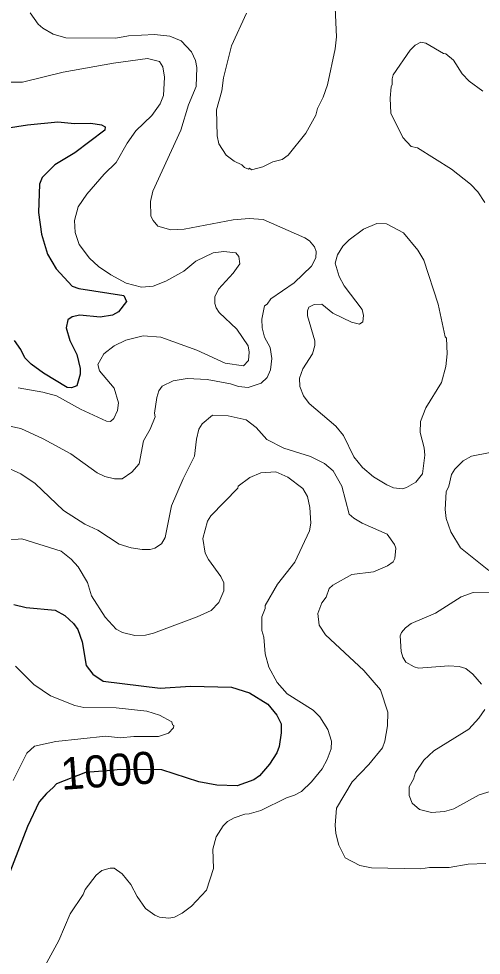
# Model space of a CAD drawing. Extents: x 447.8 to 473.9, y 7733.1 to 7760.8.
# Drawn here: x 455.425 to 456.578, y 7746.538 to 7748.871 of the extents above; entities that cross this region are included whole.
import ezdxf
from ezdxf.enums import TextEntityAlignment as Align

# ---------------------------------------------------------------- set-up
doc = ezdxf.new("R2010")
doc.units = 0
doc.header["$LTSCALE"] = 0.032
doc.layers.add('1', color=7, linetype='Continuous', lineweight=25)
doc.layers.add('2', color=7, linetype='Continuous', lineweight=13)
doc.layers.add('61', color=7, linetype='Continuous')

msp = doc.modelspace()

# ---------------------------------------------------------------- linework, layer by layer
at = {"layer": '1'}
for points in [[(455.3932, 7748.5984), (455.4461, 7748.6072), (455.5218, 7748.6144), (455.5635, 7748.6105), (455.6048, 7748.6111), (455.6308, 7748.6071), (455.6399, 7748.6018), (455.6394, 7748.5941), (455.5646, 7748.5376), (455.515, 7748.5077), (455.4827, 7748.4756), (455.4768, 7748.4588), (455.4738, 7748.3888), (455.4813, 7748.3348), (455.4964, 7748.2847), (455.5176, 7748.2483), (455.558, 7748.2048), (455.5747, 7748.199), (455.6864, 7748.1816), (455.6938, 7748.167), (455.6735, 7748.1409), (455.6584, 7748.133), (455.6275, 7748.1279), (455.5769, 7748.1326), (455.5575, 7748.1288), (455.5472, 7748.121), (455.5432, 7748.1015), (455.5525, 7748.0698), (455.5698, 7748.0352), (455.5779, 7747.9999), (455.578, 7747.9857), (455.5694, 7747.9568), (455.5561, 7747.9519), (455.5454, 7747.953), (455.4862, 7747.9883), (455.4556, 7748.0105), (455.4396, 7748.0266), (455.4298, 7748.0474), (455.4139, 7748.0695)], [(455.4124, 7747.4119), (455.4434, 7747.4048), (455.5155, 7747.3976), (455.5399, 7747.3843), (455.5611, 7747.3647), (455.5723, 7747.3499), (455.5827, 7747.319), (455.5929, 7747.2599), (455.6094, 7747.2386), (455.6348, 7747.2206), (455.7777, 7747.2037), (455.8532, 7747.2083), (455.9555, 7747.2059), (456.0001, 7747.1917), (456.0461, 7747.1635), (456.0685, 7747.1362), (456.0789, 7747.1151), (456.079, 7747.0924), (456.0741, 7747.0585), (456.0682, 7747.0421), (456.0501, 7747.0144), (456.025, 7746.9853), (456.011, 7746.9748), (455.9691, 7746.9602), (455.9188, 7746.9617), (455.8735, 7746.97), (455.7817, 7747), (455.6778, 7747.0006), (455.656, 7746.9988), (455.5913, 7746.9935), (455.5188, 7746.9649), (455.5109, 7746.9562), (455.4937, 7746.9414), (455.4754, 7746.9202), (455.4468, 7746.8588), (455.4021, 7746.7451)]]:
    msp.add_lwpolyline(points, dxfattribs=at)
at = {"layer": '2'}
for points in [[(455.4528, 7748.8864), (455.4733, 7748.8579), (455.4845, 7748.8475), (455.5107, 7748.8327), (455.5423, 7748.8239), (455.6669, 7748.8228), (455.6987, 7748.8283), (455.7632, 7748.8316), (455.8013, 7748.8276), (455.8296, 7748.8162), (455.8559, 7748.7886), (455.8657, 7748.7671), (455.8689, 7748.7501), (455.8672, 7748.7027), (455.8479, 7748.6571), (455.8287, 7748.5941), (455.7587, 7748.4414), (455.7536, 7748.4163), (455.7544, 7748.3796), (455.7599, 7748.3685), (455.7718, 7748.3548), (455.8042, 7748.3451), (455.8369, 7748.3471), (455.9594, 7748.3707), (455.9996, 7748.374), (456.0342, 7748.3715), (456.1381, 7748.3256), (456.1495, 7748.3177), (456.1621, 7748.3028), (456.1663, 7748.291), (456.1655, 7748.2753), (456.1548, 7748.255), (456.1116, 7748.2133), (456.0535, 7748.1735), (456.0438, 7748.1602), (456.0374, 7748.1563), (456.0312, 7748.1226), (456.0317, 7748.1015), (456.0377, 7748.0776), (456.0514, 7748.0519), (456.0558, 7748.0247), (456.0525, 7747.9963), (456.0439, 7747.9774), (456.0292, 7747.9635), (455.9972, 7747.9523), (455.9726, 7747.9552), (455.9526, 7747.9618), (455.8943, 7747.9724), (455.8448, 7747.9748), (455.8099, 7747.9692), (455.7826, 7747.9556), (455.7744, 7747.9447), (455.7688, 7747.9277), (455.7632, 7747.8889), (455.7646, 7747.8796), (455.7522, 7747.8487), (455.7359, 7747.8197), (455.7246, 7747.7623), (455.7068, 7747.742), (455.6828, 7747.7247), (455.6631, 7747.7247), (455.6391, 7747.7305), (455.6205, 7747.7401), (455.5547, 7747.7871), (455.4859, 7747.8248), (455.43, 7747.8503), (455.3722, 7747.8624)], [(455.9925, 7748.8848), (455.9554, 7748.8037), (455.9356, 7748.7244), (455.9313, 7748.6919), (455.9179, 7748.644), (455.9195, 7748.5796), (455.9238, 7748.5596), (455.9419, 7748.5312), (455.9622, 7748.5161), (455.9812, 7748.5074), (455.9873, 7748.5004), (455.9978, 7748.4968), (456.0005, 7748.4987), (456.0053, 7748.4951), (456.0335, 7748.5027), (456.0582, 7748.5149), (456.0815, 7748.5203), (456.0969, 7748.5314), (456.1409, 7748.5866), (456.1654, 7748.631), (456.1697, 7748.6475), (456.1839, 7748.6761), (456.1948, 7748.7066), (456.2136, 7748.7963), (456.2168, 7748.8262), (456.2137, 7748.8983)], [(456.5818, 7748.6906), (456.5479, 7748.7154), (456.5303, 7748.734), (456.5088, 7748.768), (456.49, 7748.7842), (456.4841, 7748.7847), (456.4402, 7748.8108), (456.4277, 7748.813), (456.4135, 7748.8053), (456.4011, 7748.7929), (456.3585, 7748.7317), (456.3556, 7748.7212), (456.3563, 7748.7076), (456.3532, 7748.7019), (456.3508, 7748.6735), (456.3528, 7748.636), (456.3825, 7748.5758), (456.4032, 7748.553), (456.4188, 7748.5494), (456.5036, 7748.4967), (456.5517, 7748.459), (456.5697, 7748.4402), (456.5873, 7748.4133)], [(455.4235, 7747.9514), (455.485, 7747.9411), (455.5187, 7747.9316), (455.5787, 7747.8985), (455.6436, 7747.8684), (455.6534, 7747.8682), (455.6622, 7747.8756), (455.6711, 7747.8956), (455.6732, 7747.9141), (455.6627, 7747.9513), (455.6258, 7747.994), (455.6222, 7748.0101), (455.6366, 7748.0362), (455.6623, 7748.0565), (455.6916, 7748.0704), (455.7352, 7748.0811), (455.7791, 7748.078), (455.8687, 7748.046), (455.9394, 7748.013), (455.9852, 7748.0069), (455.9978, 7748.0199), (455.9996, 7748.0408), (455.9965, 7748.0567), (455.9682, 7748.0982), (455.9245, 7748.1397), (455.9169, 7748.1514), (455.9139, 7748.1621), (455.914, 7748.1788), (455.9232, 7748.1973), (455.9594, 7748.2373), (455.9757, 7748.2611), (455.9736, 7748.2787), (455.9658, 7748.2885), (455.9361, 7748.2913), (455.9099, 7748.2885), (455.8663, 7748.2675), (455.8366, 7748.2428), (455.7917, 7748.2173), (455.7598, 7748.2047), (455.7304, 7748.2024), (455.6923, 7748.2129), (455.6544, 7748.2332), (455.6239, 7748.254), (455.6013, 7748.2744), (455.5755, 7748.3092), (455.5656, 7748.3385), (455.564, 7748.3687), (455.573, 7748.4026), (455.5947, 7748.4342), (455.6373, 7748.4837), (455.6677, 7748.5131), (455.6952, 7748.5612), (455.7163, 7748.5917), (455.7564, 7748.6299), (455.7771, 7748.6593), (455.7856, 7748.6801), (455.788, 7748.726), (455.7838, 7748.7512), (455.7757, 7748.7647), (455.746, 7748.772), (455.6606, 7748.761), (455.5351, 7748.7385), (455.4344, 7748.713), (455.4009, 7748.713)], [(456.5893, 7746.7664), (456.5452, 7746.7651), (456.4981, 7746.7572), (456.4487, 7746.7571), (456.4276, 7746.7531), (456.3044, 7746.7556), (456.2755, 7746.7614), (456.2388, 7746.7812), (456.2228, 7746.8122), (456.2153, 7746.8417), (456.2137, 7746.8624), (456.2169, 7746.9043), (456.2562, 7746.9703), (456.2976, 7747.0134), (456.3321, 7747.0547), (456.3376, 7747.0712), (456.3443, 7747.1098), (456.3451, 7747.1434), (456.3272, 7747.1998), (456.2852, 7747.2474), (456.1894, 7747.3361), (456.1742, 7747.3604), (456.1704, 7747.3892), (456.1802, 7747.4163), (456.1911, 7747.4306), (456.1991, 7747.4517), (456.2081, 7747.4602), (456.2557, 7747.4866), (456.3096, 7747.4933), (456.3445, 7747.5086), (456.3583, 7747.5183), (456.3628, 7747.5263), (456.3651, 7747.5524), (456.3619, 7747.5611), (456.3432, 7747.5875), (456.2815, 7747.6146), (456.2604, 7747.6267), (456.249, 7747.6374), (456.2303, 7747.7064), (456.2086, 7747.7449), (456.1876, 7747.763), (456.1522, 7747.7806), (456.0855, 7747.8013), (456.0434, 7747.8233), (456.0171, 7747.8529), (455.9916, 7747.872), (455.9468, 7747.8818), (455.9077, 7747.8835), (455.8821, 7747.8619), (455.8739, 7747.8484), (455.8679, 7747.8237), (455.8633, 7747.7815), (455.8344, 7747.7251), (455.8054, 7747.6574), (455.7901, 7747.5789), (455.7808, 7747.5629), (455.7637, 7747.5525), (455.7522, 7747.5491), (455.7321, 7747.5491), (455.7054, 7747.5535), (455.6752, 7747.5626), (455.6216, 7747.5972)], [(456.6001, 7747.7903), (456.5542, 7747.7819), (456.5331, 7747.7696), (456.5123, 7747.7491), (456.5041, 7747.7358), (456.4976, 7747.7071), (456.4903, 7747.6923), (456.4878, 7747.649), (456.491, 7747.6263), (456.5025, 7747.5933), (456.5266, 7747.5535), (456.5966, 7747.4967)], [(455.6216, 7747.5972), (455.5893, 7747.612), (455.5361, 7747.6461), (455.4658, 7747.7133), (455.43, 7747.7373), (455.3858, 7747.7574)], [(455.87, 7747.3811), (455.9045, 7747.3971), (455.9238, 7747.4171), (455.9363, 7747.4464), (455.9363, 7747.4657), (455.929, 7747.4816), (455.8975, 7747.5245), (455.8899, 7747.5398), (455.8839, 7747.5763), (455.8955, 7747.6196), (455.904, 7747.6328), (455.9713, 7747.7015), (455.9719, 7747.707), (456.0013, 7747.7284), (456.0283, 7747.7399), (456.066, 7747.7422), (456.096, 7747.7296), (456.1328, 7747.7011), (456.1451, 7747.6811), (456.151, 7747.6539), (456.1527, 7747.6148), (456.1496, 7747.5958), (456.1134, 7747.5173), (456.07, 7747.4627), (456.0392, 7747.4093), (456.0396, 7747.4017), (456.031, 7747.3814), (456.0309, 7747.347), (456.0357, 7747.331), (456.039, 7747.289), (456.0484, 7747.256), (456.0694, 7747.2173), (456.094, 7747.1892), (456.1591, 7747.149), (456.1757, 7747.1325), (456.1959, 7747.1004), (456.2048, 7747.0713), (456.204, 7747.0521), (456.1938, 7747.0255), (456.1813, 7747.0026), (456.1549, 7746.9701), (456.1296, 7746.9462), (456.1121, 7746.9368), (456.0925, 7746.9306), (456.0287, 7746.8985), (455.9995, 7746.8903), (455.9889, 7746.89), (455.9619, 7746.8804), (455.9456, 7746.8713), (455.9345, 7746.8603), (455.9172, 7746.8335), (455.9083, 7746.8023), (455.9106, 7746.754), (455.893, 7746.7006), (455.8551, 7746.6607), (455.8324, 7746.6434), (455.8132, 7746.6331), (455.7989, 7746.6308), (455.7754, 7746.6334), (455.7638, 7746.6381), (455.7409, 7746.6546), (455.7203, 7746.6845), (455.7042, 7746.7144), (455.6822, 7746.741), (455.6623, 7746.7548), (455.6529, 7746.755), (455.6323, 7746.7493), (455.6178, 7746.7377), (455.59, 7746.702), (455.5852, 7746.6898), (455.553, 7746.6414), (455.5243, 7746.5746), (455.4797, 7746.4931)], [(455.1371, 7747.4028), (455.1379, 7747.4839), (455.13, 7747.5464), (455.132, 7747.5839), (455.1491, 7747.6162), (455.1691, 7747.6253), (455.2531, 7747.6028), (455.2943, 7747.5798), (455.3155, 7747.5724), (455.395, 7747.5724), (455.4321, 7747.5755), (455.5305, 7747.545), (455.5558, 7747.5247), (455.5725, 7747.5055), (455.596, 7747.4667), (455.6059, 7747.4339), (455.6401, 7747.3802), (455.668, 7747.3507), (455.6836, 7747.342), (455.7144, 7747.3351), (455.7404, 7747.3358), (455.7609, 7747.341), (455.87, 7747.3811)], [(456.5997, 7747.4409), (456.558, 7747.4415), (456.5279, 7747.4313), (456.4637, 7747.3903), (456.4037, 7747.365), (456.3889, 7747.3539), (456.3789, 7747.3421), (456.3756, 7747.3338), (456.3781, 7747.2951), (456.3822, 7747.2808), (456.39, 7747.2687), (456.4108, 7747.2565), (456.4216, 7747.2533), (456.4969, 7747.259), (456.523, 7747.2573), (456.5399, 7747.2524), (456.557, 7747.2386), (456.5791, 7747.2139)], [(455.4107, 7746.9737), (455.4445, 7747.042), (455.4636, 7747.0593), (455.5175, 7747.0705), (455.6417, 7747.0841), (455.6776, 7747.0801), (455.7113, 7747.0834), (455.7734, 7747.0834), (455.7984, 7747.0914), (455.8107, 7747.1045), (455.8112, 7747.1103), (455.8081, 7747.1125), (455.8065, 7747.12), (455.7755, 7747.1367), (455.7439, 7747.1466), (455.6676, 7747.1546), (455.5868, 7747.1551), (455.5643, 7747.16), (455.5041, 7747.1848), (455.4626, 7747.2127), (455.4164, 7747.2581)], [(456.5871, 7747.1508), (456.5719, 7747.129), (456.5471, 7747.1017), (456.4599, 7747.0471), (456.4346, 7747.0246), (456.4138, 7746.9938), (456.4093, 7746.977), (456.3982, 7746.9576), (456.3982, 7746.9361), (456.4056, 7746.9172), (456.4244, 7746.9017), (456.4538, 7746.8942), (456.4867, 7746.8963), (456.5096, 7746.9027), (456.5725, 7746.9381), (456.6301, 7746.9551)]]:
    msp.add_lwpolyline(points, dxfattribs=at)
msp.add_lwpolyline([(456.4901, 7748.0053), (456.4934, 7748.0361), (456.4918, 7748.0754), (456.4882, 7748.0786), (456.4709, 7748.1598), (456.4353, 7748.27), (456.42, 7748.2951), (456.3838, 7748.3376), (456.3419, 7748.3602), (456.318, 7748.3611), (456.2847, 7748.3469), (456.2487, 7748.3207), (456.2327, 7748.3047), (456.2197, 7748.2827), (456.2138, 7748.262), (456.224, 7748.2293), (456.2362, 7748.2061), (456.2808, 7748.147), (456.2842, 7748.1318), (456.2824, 7748.1166), (456.2742, 7748.1102), (456.2543, 7748.1155), (456.2078, 7748.1379), (456.1809, 7748.1599), (456.1618, 7748.1597), (456.1479, 7748.1531), (456.1448, 7748.1438), (456.1452, 7748.131), (456.1631, 7748.0685), (456.1631, 7748.0572), (456.1575, 7748.0365), (456.1335, 7747.9995), (456.1247, 7747.976), (456.1253, 7747.9551), (456.1345, 7747.9316), (456.1493, 7747.9124), (456.2153, 7747.8566), (456.2344, 7747.8328), (456.26, 7747.7802), (456.2819, 7747.7533), (456.3096, 7747.7304), (456.3425, 7747.7098), (456.3589, 7747.7027), (456.3819, 7747.7005), (456.3919, 7747.7031), (456.4153, 7747.7168), (456.4316, 7747.7378), (456.4372, 7747.7838), (456.4356, 7747.8022), (456.4261, 7747.8402), (456.4267, 7747.8676), (456.4398, 7747.902), (456.4792, 7747.965)], close=True, dxfattribs=at)

# ---------------------------------------------------------------- texts
at = {"layer": '61'}
msp.add_text('1000', height=0.08, rotation=4.109, dxfattribs=at).set_placement((455.6503, 7746.9585), align=Align.CENTER)

doc.saveas('drawing.dxf')
